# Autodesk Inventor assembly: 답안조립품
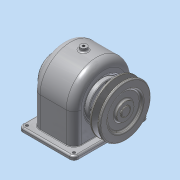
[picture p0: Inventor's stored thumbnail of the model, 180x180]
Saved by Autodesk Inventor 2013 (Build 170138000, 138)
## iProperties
Created: 2016-01
Part Number: 답안조립품
Document SubType Name: Assembly
Designer: dgall
Author: dgall
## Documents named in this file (16)
- C:\Users\dgall\Desktop\460105V1023\답안조립품.iam
- C:\Users\dgall\Desktop\460105V1023\1-본체.ipt
- C:\Users\dgall\Desktop\460105V1023\뒤커버.ipt
- C:\Users\dgall\Desktop\460105V1023\베어링 6203.ipt
- C:\Users\dgall\Desktop\460105V1023\앞커버.ipt
- C:\Users\dgall\Desktop\460105V1023\부시1.ipt
- C:\Users\dgall\Desktop\460105V1023\축.ipt
- C:\Users\dgall\Desktop\460105V1023\키 - 6 x 6 x 22.ipt
- C:\Users\dgall\Desktop\460105V1023\키 - 5 x 5 x 18.ipt
- C:\Users\dgall\Desktop\460105V1023\스퍼기어.ipt
- C:\Users\dgall\Desktop\460105V1023\오일씰 28 40 8.ipt
- C:\Users\dgall\Desktop\460105V1023\부시2.ipt
- C:\Users\dgall\Desktop\460105V1023\V-벨트풀리.ipt
- C:\Users\dgall\Desktop\460105V1023\멈춤나사 - M4x10.ipt
- C:\Users\dgall\Desktop\460105V1023\볼트 M3 x 10.ipt
- C:\Users\dgall\Desktop\460105V1023\볼트 M3 x 8.ipt
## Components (10 placed, 4 different names)
1. 1-본체:1
2. V-벨트풀리:1
3. ISO 4762 M3 x 10:1
4. ISO 4762 M3 x 10:2
5. ISO 4762 M3 x 10:3
6. ISO 4762 M3 x 10:4
7. ISO 4762 M3 x 8:1
8. ISO 4762 M3 x 8:2
9. ISO 4762 M3 x 8:3
10. ISO 4762 M3 x 8:4
